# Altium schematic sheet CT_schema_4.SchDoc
size 313 x 200 mm
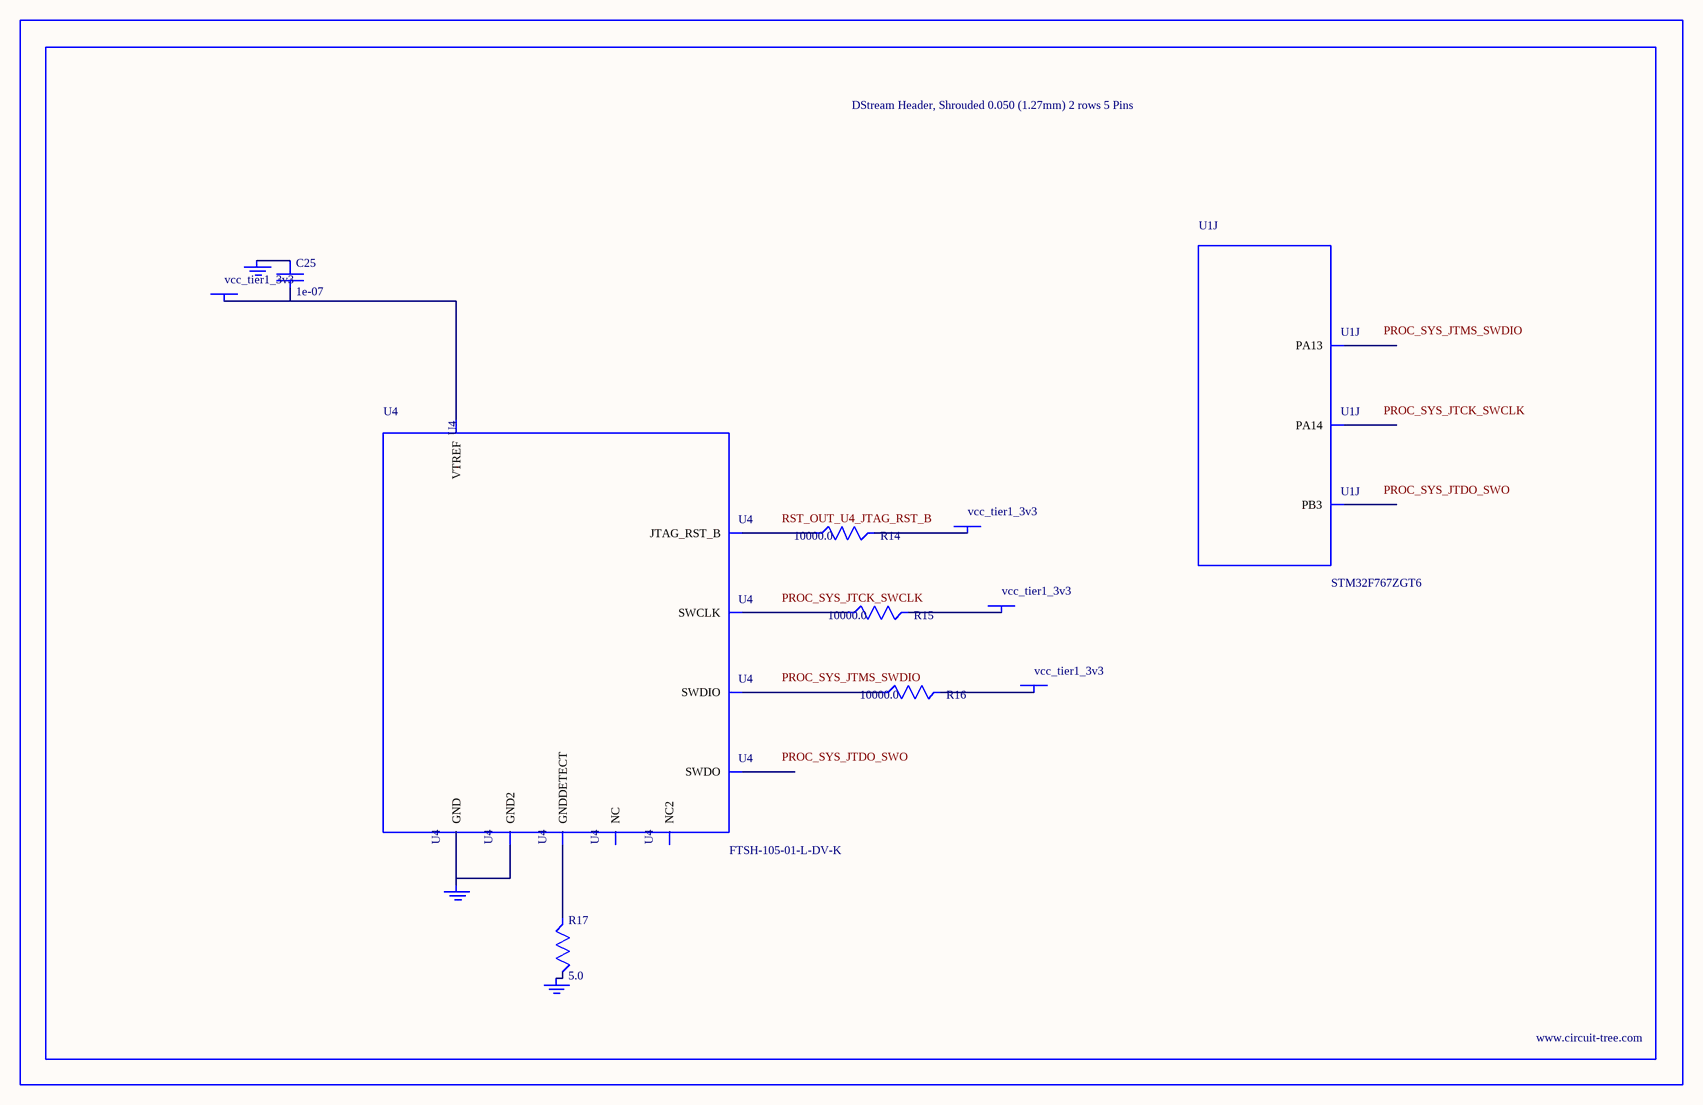
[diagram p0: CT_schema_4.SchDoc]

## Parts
BORDER3  (no value)
C25  1e-07  [C0402]
GND_INSTANCE_3_0  (no value)
GND_INSTANCE_3_1  (no value)
GND_INSTANCE_3_2  (no value)
POWER_INSTANCE_3_0  vcc_tier1_3v3
POWER_INSTANCE_3_1  vcc_tier1_3v3
POWER_INSTANCE_3_2  vcc_tier1_3v3
POWER_INSTANCE_3_3  vcc_tier1_3v3
R14  10000.0  [R0603]
R15  10000.0  [R0603]
R16  10000.0  [R0603]
R17  5.0  [R0603]
U1  STM32F767ZGT6  [LQFP144]  (part J of 13)
U4  FTSH-105-01-L-DV-K  [SAMTEC_FTSH-105-01-L-DV-K]

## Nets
NetC25_1: C25.1 GND_INSTANCE_3_0.0(GND)
NetC25_2: C25.2 POWER_INSTANCE_3_0.0(PWR) U4.1(VTREF)
NetGND_INSTANCE_3_1_0: GND_INSTANCE_3_1.0(GND) R17.2
NetGND_INSTANCE_3_2_0: GND_INSTANCE_3_2.0(GND) U4.3(GND) U4.5(GND2)
NetPOWER_INSTANCE_3_1_0: POWER_INSTANCE_3_1.0(PWR) R16.2
NetPOWER_INSTANCE_3_2_0: POWER_INSTANCE_3_2.0(PWR) R15.2
NetPOWER_INSTANCE_3_3_0: POWER_INSTANCE_3_3.0(PWR) R14.2
NetR14_1: R14.1 U4.10(JTAG_RST_B)
NetR15_1: R15.1 U4.4(SWCLK)
NetR16_1: R16.1 U4.2(SWDIO)
NetR17_1: R17.1 U4.9(GNDDETECT)

Not connected (* = marked no-connect by the designer): U1 105(PA13) 109(PA14) 133(PB3); U4 6(SWDO) 7(NC) 8(NC2)

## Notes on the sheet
- Labels drawn without touching a wire or pin: PROC_SYS_JTCK_SWCLK, PROC_SYS_JTDO_SWO, PROC_SYS_JTMS_SWDIO, RST_OUT_U4_JTAG_RST_B

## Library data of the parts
BORDER3 = BORDER_PAGE3
C25 = C0402C104K3RACTU
GND_INSTANCE_3_0-GND_INSTANCE_3_2 = GND
POWER_INSTANCE_3_0-POWER_INSTANCE_3_3 = PWR
R14-R16 = RC0603JR-0710KL
R17 = ERJ-3GEYJ5R1V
